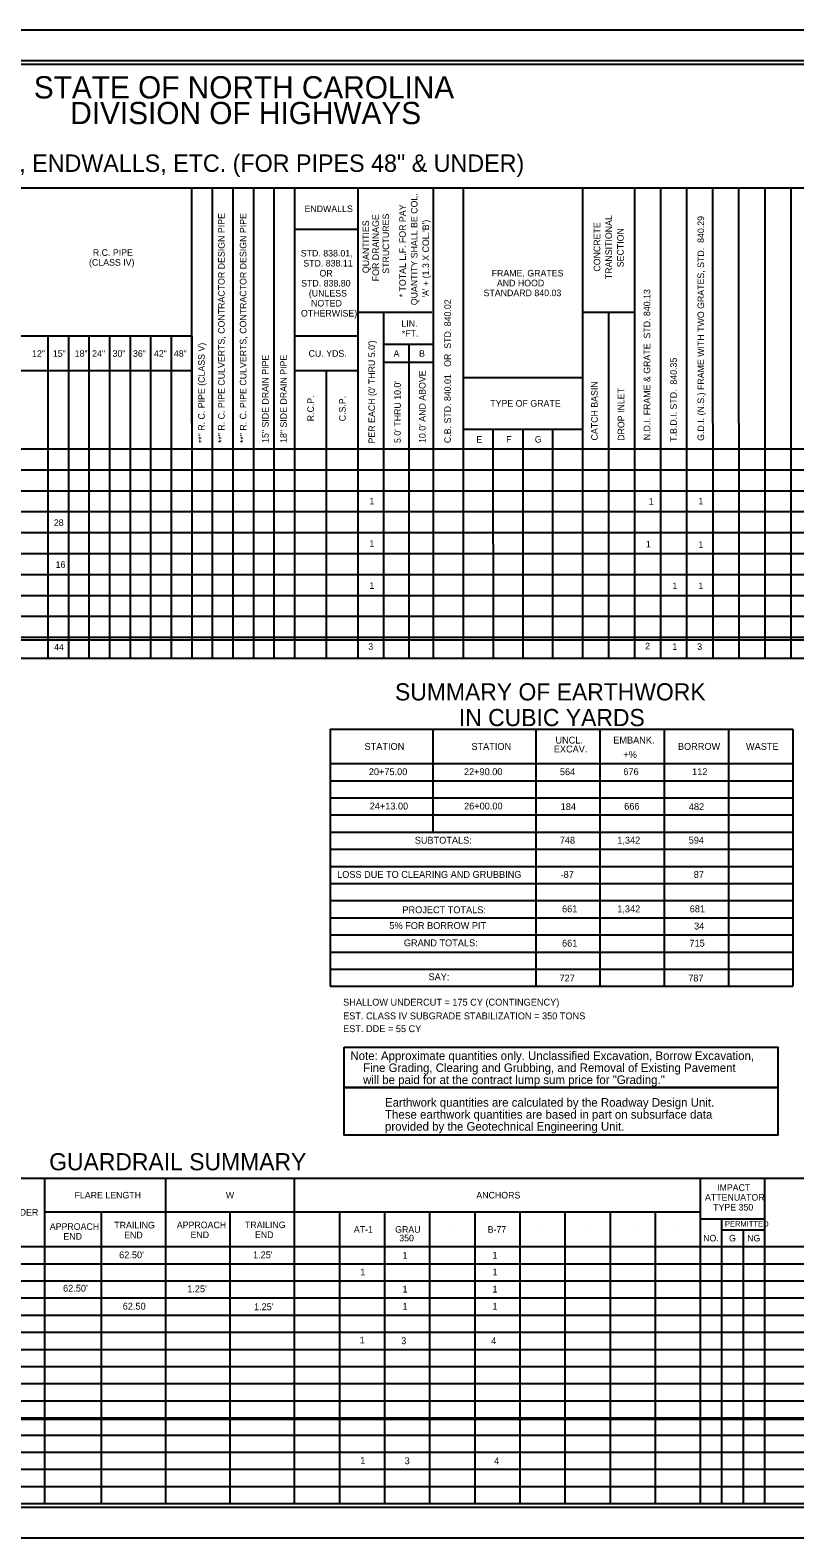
# Model space of a CAD drawing. Extents: x 573867 to 573943.6, y -53322.8 to -53274.5.
# Drawn here: x 573882.72 to 573893.88, y -53322.27 to -53300.27 of the extents above; entities that cross this region are included whole.
import ezdxf

# ---------------------------------------------------------------- set-up
doc = ezdxf.new("R2010")
doc.units = 0
for name, color, linetype in [('Default', 7, 'Continuous'), ('Prop Grid Mask', 7, 'Continuous'), ('Prop XSC Text', 7, 'Continuous'), ('Sheet Cutting Line CELL', 7, 'Continuous'), ('Sheet Pipe Summary CELL', 7, 'Continuous'), ('Sheet Pipe Summary Grid CELL', 7, 'Continuous'), ('Sheet Plot Border Inside CELL', 7, 'Continuous'), ('Sheet Plot Border Outside CELL', 7, 'Continuous'), ('Sheet Summary Combination CELL', 7, 'Continuous'), ('Sheet Summary Combination Grid CELL', 7, 'Continuous'), ('Sheet Summary Earthwork CELL', 7, 'Continuous'), ('Sheet Summary Guardrail CELL', 7, 'Continuous')]:
    doc.layers.add(name, color=color, linetype=linetype)

msp = doc.modelspace()

# ---------------------------------------------------------------- linework, layer by layer
at = {"layer": 'Prop Grid Mask'}
for points in [[(573887.306, -53315.112), (573893.635, -53315.112), (573893.635, -53315.701), (573887.306, -53315.701)], [(573887.306, -53315.701), (573893.635, -53315.701), (573893.635, -53316.396), (573887.306, -53316.396)]]:
    msp.add_lwpolyline(points, close=True, dxfattribs=at)
at = {"layer": 'Sheet Cutting Line CELL'}
for p, q in [((573900.663, -53300.271), (573866.983, -53300.271)), ((573866.983, -53322.271), (573900.663, -53322.271))]:
    msp.add_line(p, q, dxfattribs=at)
at = {"layer": 'Sheet Pipe Summary Grid CELL'}
for p, q in [((573900.323, -53302.578), (573870.323, -53302.58)), ((573885.087, -53309.44), (573885.086, -53302.578)), ((573885.387, -53309.44), (573885.386, -53302.578)), ((573885.687, -53309.44), (573885.686, -53302.578)), ((573885.987, -53309.44), (573885.986, -53302.578)), ((573886.287, -53309.44), (573886.286, -53302.578)), ((573886.587, -53309.44), (573886.586, -53302.578)), ((573886.587, -53309.44), (573886.586, -53302.578)), ((573886.587, -53309.44), (573886.586, -53302.578)), ((573887.512, -53309.44), (573887.511, -53302.579)), ((573888.612, -53309.44), (573888.611, -53302.579)), ((573888.612, -53309.44), (573888.611, -53302.579)), ((573889.049, -53309.44), (573889.048, -53302.579)), ((573890.788, -53309.44), (573890.787, -53302.579)), ((573891.548, -53309.44), (573891.547, -53302.579)), ((573891.928, -53309.44), (573891.927, -53302.579)), ((573892.308, -53309.44), (573892.307, -53302.579)), ((573892.688, -53309.44), (573892.687, -53302.579)), ((573893.068, -53309.44), (573893.067, -53302.579)), ((573893.448, -53309.44), (573893.447, -53302.579)), ((573893.828, -53309.44), (573893.827, -53302.579)), ((573887.511, -53303.178), (573886.586, -53303.178)), ((573888.586, -53304.393), (573887.512, -53304.393)), ((573887.884, -53309.44), (573887.883, -53304.393)), ((573891.548, -53304.393), (573890.788, -53304.393)), ((573891.168, -53309.44), (573891.168, -53304.393)), ((573885.087, -53304.736), (573874.737, -53304.737)), ((573882.987, -53309.44), (573882.987, -53304.736)), ((573883.287, -53309.44), (573883.287, -53304.736)), ((573883.587, -53309.44), (573883.587, -53304.736)), ((573883.887, -53309.44), (573883.887, -53304.736)), ((573884.187, -53309.44), (573884.187, -53304.736)), ((573884.487, -53309.44), (573884.487, -53304.736)), ((573884.787, -53309.44), (573884.787, -53304.736)), ((573885.087, -53309.44), (573885.087, -53304.736)), ((573887.511, -53304.735), (573886.586, -53304.735)), ((573888.611, -53304.857), (573887.883, -53304.857)), ((573888.255, -53309.44), (573888.254, -53304.857)), ((573885.087, -53305.244), (573878.337, -53305.244)), ((573887.511, -53305.243), (573886.586, -53305.243)), ((573887.05, -53309.44), (573887.049, -53305.243)), ((573888.611, -53305.121), (573887.883, -53305.121)), ((573890.787, -53305.344), (573889.048, -53305.344)), ((573890.787, -53306.1), (573889.048, -53306.1)), ((573889.483, -53309.44), (573889.482, -53306.1)), ((573889.918, -53309.44), (573889.917, -53306.1)), ((573890.353, -53309.44), (573890.353, -53306.1)), ((573900.323, -53306.386), (573870.323, -53306.386)), ((573900.323, -53306.692), (573870.323, -53306.692)), ((573900.323, -53306.997), (573870.323, -53306.997)), ((573900.323, -53307.302), (573870.323, -53307.302)), ((573900.323, -53307.608), (573870.323, -53307.608)), ((573900.323, -53307.913), (573870.323, -53307.913)), ((573900.323, -53308.219), (573870.323, -53308.219)), ((573900.323, -53308.524), (573870.323, -53308.524)), ((573900.323, -53308.829), (573870.323, -53308.829)), ((573900.323, -53309.135), (573870.323, -53309.135)), ((573900.323, -53309.44), (573870.323, -53309.44))]:
    msp.add_line(p, q, dxfattribs=at)
at = {"layer": 'Sheet Plot Border Inside CELL'}
msp.add_lwpolyline([(573900.573, -53300.72), (573867.243, -53300.72), (573867.243, -53321.822), (573900.573, -53321.822)], close=True, dxfattribs=at)
at = {"layer": 'Sheet Plot Border Outside CELL'}
msp.add_lwpolyline([(573900.663, -53300.271), (573866.983, -53300.271), (573866.983, -53322.271), (573900.663, -53322.271)], close=True, dxfattribs=at)
at = {"layer": 'Sheet Summary Combination CELL'}
for p, q in [((573889.175, -53310.474), (573889.175, -53310.474)), ((573889.3, -53310.476), (573889.3, -53310.476)), ((573889.481, -53310.472), (573889.481, -53310.472)), ((573889.593, -53310.474), (573889.593, -53310.474))]:
    msp.add_line(p, q, dxfattribs=at)
msp.add_lwpolyline([(573900.323, -53300.771), (573870.323, -53300.771), (573870.323, -53321.771), (573900.323, -53321.771)], close=True, dxfattribs=at)
at = {"layer": 'Sheet Summary Combination Grid CELL'}
for p, q in [((573900.323, -53309.171), (573870.323, -53309.171)), ((573887.101, -53310.473), (573893.853, -53310.473)), ((573887.101, -53310.473), (573887.101, -53314.223)), ((573888.601, -53310.473), (573888.601, -53311.973)), ((573890.101, -53310.473), (573890.101, -53314.223)), ((573891.039, -53310.473), (573891.039, -53314.223)), ((573891.977, -53310.473), (573891.977, -53314.223)), ((573892.915, -53310.473), (573892.915, -53314.223)), ((573893.853, -53310.473), (573893.853, -53314.223)), ((573887.101, -53310.973), (573893.853, -53310.973)), ((573887.101, -53311.223), (573893.853, -53311.223)), ((573887.101, -53311.473), (573893.853, -53311.473)), ((573887.101, -53311.723), (573893.853, -53311.723)), ((573887.101, -53311.973), (573893.853, -53311.973)), ((573887.101, -53312.223), (573893.853, -53312.223)), ((573887.101, -53312.473), (573893.853, -53312.473)), ((573887.101, -53312.723), (573893.853, -53312.723)), ((573887.101, -53312.973), (573893.853, -53312.973)), ((573887.101, -53313.223), (573893.853, -53313.223)), ((573887.101, -53313.223), (573893.853, -53313.223)), ((573887.101, -53313.473), (573893.853, -53313.473)), ((573887.101, -53313.473), (573893.853, -53313.473)), ((573887.101, -53313.723), (573893.853, -53313.723)), ((573887.101, -53313.973), (573893.853, -53313.973)), ((573887.101, -53313.973), (573893.853, -53313.973)), ((573887.101, -53314.223), (573893.853, -53314.223))]:
    msp.add_line(p, q, dxfattribs=at)
at = {"layer": 'Sheet Summary Guardrail CELL'}
for p, q in [((573870.323, -53317.021), (573900.323, -53317.021)), ((573882.933, -53317.021), (573882.933, -53321.771)), ((573884.699, -53317.021), (573884.699, -53321.771)), ((573886.579, -53317.021), (573886.579, -53321.771)), ((573892.501, -53317.021), (573892.501, -53321.771)), ((573893.441, -53317.021), (573893.441, -53321.771)), ((573892.501, -53317.521), (573882.933, -53317.521)), ((573883.759, -53317.521), (573883.759, -53321.771)), ((573885.639, -53317.521), (573885.639, -53321.771)), ((573887.237, -53317.521), (573887.237, -53321.771)), ((573887.895, -53317.521), (573887.895, -53321.771)), ((573888.553, -53317.521), (573888.553, -53321.771)), ((573889.211, -53317.521), (573889.211, -53321.771)), ((573889.869, -53317.521), (573889.869, -53321.771)), ((573890.527, -53317.521), (573890.527, -53321.771)), ((573891.185, -53317.521), (573891.185, -53321.771)), ((573891.843, -53317.521), (573891.843, -53321.771)), ((573892.501, -53317.616), (573893.441, -53317.616)), ((573892.814, -53317.616), (573892.814, -53321.771)), ((573893.263, -53317.516), (573893.263, -53317.516)), ((573887.566, -53317.771), (573887.566, -53317.771)), ((573888.224, -53317.771), (573888.224, -53317.771)), ((573888.882, -53317.771), (573888.882, -53317.771)), ((573889.54, -53317.771), (573889.54, -53317.771)), ((573890.198, -53317.771), (573890.198, -53317.771)), ((573890.856, -53317.771), (573890.856, -53317.771)), ((573891.514, -53317.771), (573891.514, -53317.771)), ((573892.172, -53317.771), (573892.172, -53317.771)), ((573892.814, -53317.776), (573893.441, -53317.776)), ((573893.127, -53317.776), (573893.127, -53321.771)), ((573870.323, -53318.021), (573900.323, -53318.021)), ((573870.323, -53318.271), (573900.323, -53318.271)), ((573870.323, -53318.521), (573900.323, -53318.521)), ((573870.323, -53318.771), (573900.323, -53318.771)), ((573870.323, -53319.021), (573900.323, -53319.021)), ((573870.323, -53319.271), (573900.323, -53319.271)), ((573870.323, -53319.521), (573900.323, -53319.521)), ((573876.353, -53319.771), (573900.323, -53319.771)), ((573870.323, -53320.021), (573900.323, -53320.021)), ((573870.323, -53320.271), (573900.323, -53320.271)), ((573870.323, -53320.521), (573900.323, -53320.521)), ((573870.323, -53320.539), (573900.323, -53320.539)), ((573876.353, -53320.771), (573900.323, -53320.771)), ((573870.323, -53321.021), (573900.323, -53321.021)), ((573870.323, -53321.271), (573900.323, -53321.271)), ((573870.323, -53321.521), (573900.323, -53321.521)), ((573870.323, -53321.771), (573900.323, -53321.771))]:
    msp.add_line(p, q, dxfattribs=at)

# ---------------------------------------------------------------- texts
at = {"layer": 'Default'}
for s, p in [('+%', (573891.38, -53310.892)), ('20+75.00', (573887.666, -53311.142)), ('22+90.00', (573889.054, -53311.142)), ('564', (573890.454, -53311.142)), ('676', (573891.38, -53311.142)), ('112', (573892.383, -53311.142)), ('24+13.00', (573887.679, -53311.643)), ('26+00.00', (573889.056, -53311.643)), ('184', (573890.466, -53311.651)), ('666', (573891.392, -53311.647)), ('482', (573892.335, -53311.652)), ('748', (573890.452, -53312.141)), ('1,342', (573891.291, -53312.141)), ('594', (573892.333, -53312.141)), ('LOSS DUE TO CLEARING AND GRUBBING', (573887.203, -53312.641)), ('-87', (573890.464, -53312.641)), ('87', (573892.407, -53312.641)), ('661', (573890.485, -53313.143)), ('1,342', (573891.291, -53313.143)), ('681', (573892.348, -53313.143)), ('34', (573892.412, -53313.394)), ('661', (573890.485, -53313.644)), ('715', (573892.344, -53313.644)), ('727', (573890.449, -53314.153)), ('787', (573892.326, -53314.153)), ('SHALLOW UNDERCUT = 175 CY (CONTINGENCY)', (573887.291, -53314.505)), ('EST. CLASS IV SUBGRADE STABILIZATION = 350 TONS', (573887.291, -53314.705)), ('EST. DDE = 55 CY', (573887.291, -53314.892)), ("62.50'", (573884.023, -53318.192)), ("1.25'", (573885.976, -53318.192)), ('1', (573888.157, -53318.198)), ('1', (573889.469, -53318.198)), ('1', (573887.541, -53318.442)), ('1', (573889.469, -53318.442)), ("62.50'", (573883.205, -53318.679)), ("1.25'", (573885.016, -53318.688)), ('1', (573888.157, -53318.692)), ('1', (573889.469, -53318.692)), ('62.50', (573884.075, -53318.941)), ("1.25'", (573885.99, -53318.949)), ('1', (573888.157, -53318.942)), ('1', (573889.469, -53318.942)), ('1', (573887.531, -53319.435)), ('3', (573888.138, -53319.445)), ('4', (573889.451, -53319.445)), ('1', (573887.541, -53321.19)), ('3', (573888.189, -53321.197)), ('4', (573889.495, -53321.197))]:
    msp.add_text(s, height=0.1, dxfattribs=at).set_placement(p)
at = {"layer": 'Prop XSC Text'}
for s, p in [('Note: Approximate quantities only. Unclassified Excavation, Borrow Excavation, ', (573887.397, -53315.299)), ('    Fine Grading, Clearing and Grubbing, and Removal of Existing Pavement ', (573887.397, -53315.474)), ('    will be paid for at the contract lump sum price for "Grading."', (573887.397, -53315.649))]:
    msp.add_text(s, height=0.125, dxfattribs=at).set_placement(p)
at = {"layer": 'Sheet Pipe Summary CELL'}
for s, height, rotation, p in [('QUANTITY SHALL BE COL.', 0.096, 90, (573888.376, -53304.285)), ('* TOTAL L.F. FOR PAY', 0.096, 90, (573888.206, -53304.17)), ('**" R. C. PIPE CULVERTS, CONTRACTOR DESIGN PIPE', 0.096, 90, (573885.563, -53306.296)), ('**" R. C. PIPE CULVERTS, CONTRACTOR DESIGN PIPE', 0.096, 90, (573885.88, -53306.296)), ('QUANTITIES', 0.096, 90, (573887.67, -53303.817)), ('FOR DRAINAGE', 0.096, 90, (573887.814, -53303.935)), ('STRUCTURES', 0.096, 90, (573887.962, -53303.826)), ("'A' + (1.3 X COL.'B')", 0.096, 90, (573888.545, -53304.174)), ('CONCRETE', 0.096, 90, (573891.043, -53303.795)), ('TRANSITIONAL', 0.096, 90, (573891.214, -53303.905)), ('SECTION', 0.096, 90, (573891.385, -53303.731)), ('C.B. STD. 840.01   OR  STD. 840.02', 0.096, 90, (573888.864, -53306.297)), ('N.D.I. FRAME & GRATE  STD. 840.13', 0.096, 90, (573891.772, -53306.255)), ('**" R. C. PIPE (CLASS V)', 0.096, 90, (573885.272, -53306.298)), ("PER EACH (0' THRU 5.0')", 0.09597, 90.0369, (573887.757, -53306.302)), ('15" SIDE DRAIN PIPE', 0.096, 90, (573886.204, -53306.294)), ('18" SIDE DRAIN PIPE', 0.096, 90, (573886.469, -53306.294)), ("10.0' AND ABOVE", 0.096, 90, (573888.494, -53306.295)), ("5.0' THRU 10.0'", 0.096, 90, (573888.133, -53306.296)), ('CATCH BASIN', 0.096, 90, (573891.006, -53306.258)), ('DROP INLET', 0.096, 90, (573891.394, -53306.263)), ('R.C.P.', 0.096, 90, (573886.865, -53305.979)), ('C.S.P.', 0.096, 90, (573887.328, -53305.979))]:
    msp.add_text(s, height=height, rotation=rotation, dxfattribs=at).set_placement(p)
for s, p in [('ENDWALLS', (573886.727, -53302.926)), ('R.C. PIPE', (573883.639, -53303.564)), ('STD. 838.01,', (573886.673, -53303.574)), ('(CLASS IV)', (573883.583, -53303.708)), ('STD. 838.11', (573886.709, -53303.72)), ('OR', (573886.946, -53303.866)), ('FRAME, GRATES', (573889.458, -53303.865)), ('STD. 838.80', (573886.679, -53304.012)), ('AND HOOD', (573889.534, -53304.009)), ('(UNLESS', (573886.791, -53304.158)), ('NOTED', (573886.823, -53304.304)), ('STANDARD 840.03', (573889.34, -53304.153)), ('OTHERWISE)', (573886.676, -53304.45)), ('*FT.', (573888.147, -53304.746)), ('LIN.', (573888.141, -53304.6)), ('12"', (573882.752, -53305.038)), ('15"', (573883.056, -53305.038)), ('18"', (573883.374, -53305.038)), ('24"', (573883.629, -53305.038)), ('30"', (573883.927, -53305.038)), ('36"', (573884.225, -53305.038)), ('42"', (573884.531, -53305.038)), ('48"', (573884.822, -53305.038)), ('CU. YDS.', (573886.787, -53305.037)), ('A', (573888.027, -53305.037)), ('B', (573888.399, -53305.037)), ('TYPE OF GRATE', (573889.438, -53305.765)), ('E', (573889.235, -53306.291)), ('F', (573889.67, -53306.291)), ('G', (573890.088, -53306.291))]:
    msp.add_text(s, height=0.096, dxfattribs=at).set_placement(p)
at = {"layer": 'Sheet Summary Combination CELL'}
for s, height, p in [('STATE OF NORTH CAROLINA', 0.325, (573882.778, -53301.268)), ('DIVISION OF HIGHWAYS', 0.325, (573883.31, -53301.643)), ('LIST OF PIPES, ENDWALLS, ETC. (FOR PIPES 48" & UNDER)', 0.254, (573880.187, -53302.339)), ('1', 0.096, (573887.675, -53307.191)), ('1', 0.096, (573891.751, -53307.195)), ('1', 0.096, (573892.475, -53307.191)), ('28', 0.096, (573883.07, -53307.506)), ('1', 0.096, (573887.675, -53307.81)), ('1', 0.096, (573891.708, -53307.82)), ('1', 0.096, (573892.475, -53307.827)), ('16', 0.096, (573883.096, -53308.117)), ('1', 0.096, (573887.675, -53308.424)), ('1', 0.096, (573892.095, -53308.427)), ('1', 0.096, (573892.475, -53308.427)), ('44', 0.096, (573883.074, -53309.322)), ('3', 0.096, (573887.657, -53309.312)), ('2', 0.096, (573891.697, -53309.307)), ('1', 0.096, (573892.094, -53309.314)), ('3', 0.096, (573892.457, -53309.314)), ('UNCL.', 0.1, (573890.389, -53310.681)), ('EMBANK.', 0.1, (573891.233, -53310.681)), ('STATION', 0.1, (573887.604, -53310.773)), ('STATION', 0.1, (573889.163, -53310.773)), ('EXCAV.', 0.1, (573890.365, -53310.811)), ('BORROW', 0.1, (573892.176, -53310.773)), ('WASTE', 0.1, (573893.169, -53310.773)), ('SUBTOTALS:', 0.1, (573888.336, -53312.142)), ('PROJECT TOTALS:', 0.1, (573888.156, -53313.157)), ('5% FOR BORROW PIT', 0.1, (573887.966, -53313.387)), ('GRAND TOTALS:', 0.1, (573888.177, -53313.639)), ('SAY: ', 0.1, (573888.537, -53314.134)), ('GUARDRAIL SUMMARY', 0.25, (573883.002, -53316.908))]:
    msp.add_text(s, height=height, dxfattribs=at).set_placement(p)
for s, height, rotation, p in [('G.D.I. (N.S.) FRAME WITH TWO GRATES, STD.  840.29', 0.096, 90, (573892.558, -53306.264)), ('T.B.D.I. STD.  840.35', 0.096, 90, (573892.16, -53306.278)), ('SUMMARY OF EARTHWORK', 0.25, 0.0119, (573888.048, -53310.052)), ('IN CUBIC YARDS', 0.25, 0.0119, (573888.98, -53310.427))]:
    msp.add_text(s, height=height, rotation=rotation, dxfattribs=at).set_placement(p)
at = {"layer": 'Sheet Summary Earthwork CELL'}
for s, p in [('Earthwork quantities are calculated by the Roadway Design Unit. ', (573887.902, -53315.98)), ('These earthwork quantities are based in part on subsurface data ', (573887.902, -53316.155)), ('provided by the Geotechnical Engineering Unit.', (573887.902, -53316.33))]:
    msp.add_text(s, height=0.125, dxfattribs=at).set_placement(p)
at = {"layer": 'Sheet Summary Guardrail CELL'}
for s, height, p in [('IMPACT', 0.096, (573892.747, -53317.207)), ('FLARE LENGTH', 0.096, (573883.372, -53317.319)), ('W', 0.096, (573885.58, -53317.319)), ('ANCHORS', 0.096, (573889.235, -53317.319)), ('ATTENUATOR', 0.096, (573892.571, -53317.351)), ('TYPE 350', 0.096, (573892.69, -53317.495)), ('SHOULDER', 0.096, (573882.13, -53317.569)), ('TRAILING', 0.096, (573883.952, -53317.756)), ('APPROACH', 0.096, (573884.864, -53317.754)), ('TRAILING', 0.096, (573885.859, -53317.752)), ('PERMITTED', 0.08, (573892.861, -53317.73)), ('APPROACH', 0.096, (573883.011, -53317.777)), ('END', 0.096, (573883.21, -53317.921)), ('END', 0.096, (573884.096, -53317.9)), ('END', 0.096, (573885.064, -53317.898)), ('END', 0.096, (573886.005, -53317.896)), ('AT-1', 0.096, (573887.447, -53317.819)), ('GRAU', 0.096, (573888.05, -53317.819)), ('350', 0.096, (573888.11, -53317.945)), ('B-77', 0.096, (573889.4, -53317.819)), ('NO.', 0.096, (573892.544, -53317.946)), ('G', 0.096, (573892.922, -53317.946)), ('NG', 0.096, (573893.186, -53317.946))]:
    msp.add_text(s, height=height, dxfattribs=at).set_placement(p)

doc.saveas('drawing.dxf')
